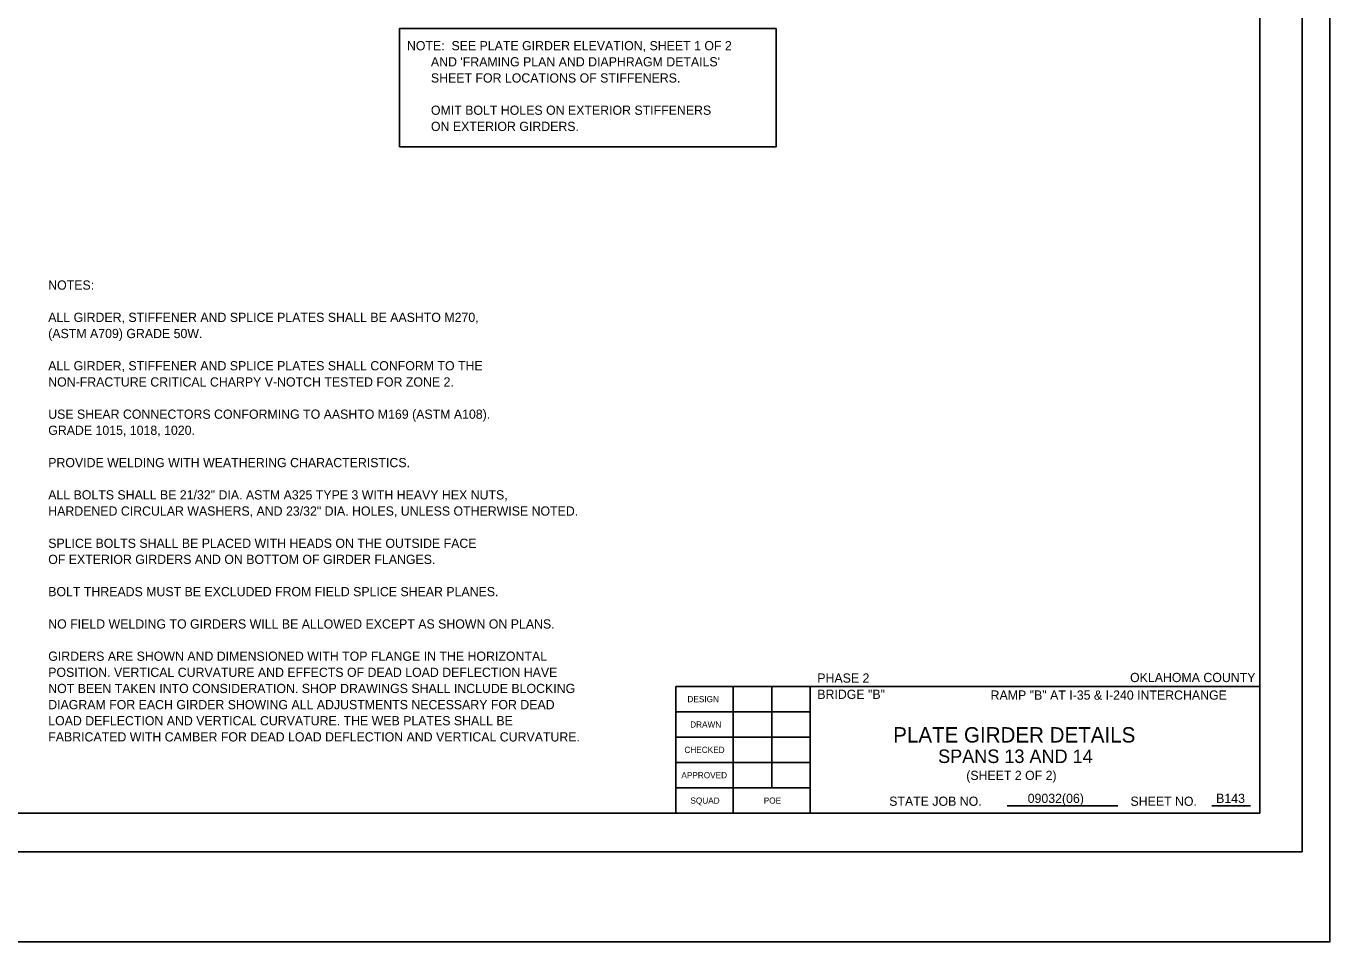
# Model space of a CAD drawing. Extents: x 4944 to 17449, y 3824 to 49087.
# Drawn here: x 14172 to 15801, y 38918 to 40062 of the extents above; entities that cross this region are included whole.
import ezdxf

# ---------------------------------------------------------------- set-up
doc = ezdxf.new("R2010")
doc.units = 0
for name, color, linetype in [('37_S_TXT', 7, 'Continuous'), ('3A', 7, 'Continuous'), ('BEAM', 7, 'Continuous'), ('DIM', 7, 'Continuous'), ('ID', 7, 'Continuous'), ('Level 14', 7, 'Continuous'), ('Level 17', 7, 'Continuous'), ('REVISED', 7, 'Continuous')]:
    doc.layers.add(name, color=color, linetype=linetype)

msp = doc.modelspace()

# ---------------------------------------------------------------- linework, layer by layer
at = {"layer": '37_S_TXT'}
msp.add_lwpolyline([(12345.1, 41222), (15801.2, 41222), (15801.2, 38917.9), (12345.1, 38917.9)], close=True, dxfattribs=at)
at = {"layer": '3A'}
msp.add_lwpolyline([(14638.8, 39911.5), (15109.3, 39911.5), (15109.3, 40059.1), (14638.8, 40059.1)], close=True, dxfattribs=at)
at = {"layer": 'DIM'}
msp.add_lwpolyline([(12502.3, 41142.8), (15766.4, 41142.8), (15766.4, 39030.7), (12502.3, 39030.7)], close=True, dxfattribs=at)
at = {"layer": 'Level 14'}
for p, q in [((14984, 39237.1), (15713.6, 39237.2)), ((14984, 39078.7), (14984, 39237.1)), ((15151.9, 39078.7), (15151.9, 39237.2)), ((15151.9, 39078.7), (15151.9, 39237.2))]:
    msp.add_line(p, q, dxfattribs=at)
msp.add_lwpolyline([(15713.6, 39078.7), (12689.5, 39078.7), (12689.5, 41094.8), (15713.6, 41094.8)], close=True, dxfattribs=at)
at = {"layer": 'Level 17'}
for p, q in [((15055.9, 39078.7), (15055.9, 39237.2)), ((15103.9, 39110.4), (15103.9, 39237.2)), ((15397.8, 39088), (15536.1, 39088)), ((15397.8, 39088), (15536.1, 39088)), ((15653.6, 39088), (15701.8, 39088)), ((15653.6, 39088), (15701.8, 39088))]:
    msp.add_line(p, q, dxfattribs=at)
for points in [[(15151.9, 39205.5), (14984, 39205.5)], [(15151.9, 39173.8), (14984, 39173.8)], [(15151.9, 39142.1), (14984, 39142.1)], [(15151.9, 39110.4), (14984, 39110.4)]]:
    msp.add_lwpolyline(points, dxfattribs=at)

# ---------------------------------------------------------------- texts
at = {"layer": '3A'}
for s, height, p in [('NOTE:  SEE PLATE GIRDER ELEVATION, SHEET 1 OF 2 ', 11.52, (14648.2, 40032)), ("       AND 'FRAMING PLAN AND DIAPHRAGM DETAILS' ", 11.52, (14648.2, 40011.9)), ('       SHEET FOR LOCATIONS OF STIFFENERS. ', 11.52, (14648.2, 39991.7)), ('       OMIT BOLT HOLES ON EXTERIOR STIFFENERS ', 11.52, (14648.2, 39951.4)), ('       ON EXTERIOR GIRDERS.', 11.52, (14648.2, 39931.2)), ('NOTES:', 11.52, (14200.1, 39732.9)), ('ALL GIRDER, STIFFENER AND SPLICE PLATES SHALL BE AASHTO M270,', 11.52, (14200.1, 39692.6)), ('(ASTM A709) GRADE 50W.', 11.52, (14200.1, 39672.4)), ('ALL GIRDER, STIFFENER AND SPLICE PLATES SHALL CONFORM TO THE', 11.52, (14200.1, 39632.1)), ('NON-FRACTURE CRITICAL CHARPY V-NOTCH TESTED FOR ZONE 2.', 11.52, (14200.1, 39611.9)), ('USE SHEAR CONNECTORS CONFORMING TO AASHTO M169 (ASTM A108).', 11.52, (14200.1, 39571.6)), ('GRADE 1015, 1018, 1020.', 11.52, (14200.1, 39551.5)), ('PROVIDE WELDING WITH WEATHERING CHARACTERISTICS.  ', 11.52, (14200.1, 39511.1)), ('ALL BOLTS SHALL BE 21/32" DIA. ASTM A325 TYPE 3 WITH HEAVY HEX NUTS, ', 11.52, (14200.1, 39470.8)), ('HARDENED CIRCULAR WASHERS, AND 23/32" DIA. HOLES, UNLESS OTHERWISE NOTED.  ', 11.52, (14200.1, 39450.6)), ('SPLICE BOLTS SHALL BE PLACED WITH HEADS ON THE OUTSIDE FACE', 11.52, (14200.1, 39410.3)), ('OF EXTERIOR GIRDERS AND ON BOTTOM OF GIRDER FLANGES.  ', 11.52, (14200.1, 39390.2)), ('BOLT THREADS MUST BE EXCLUDED FROM FIELD SPLICE SHEAR PLANES.', 11.52, (14200.1, 39349.9)), ('NO FIELD WELDING TO GIRDERS WILL BE ALLOWED EXCEPT AS SHOWN ON PLANS.', 11.52, (14200.1, 39309.5)), ('GIRDERS ARE SHOWN AND DIMENSIONED WITH TOP FLANGE IN THE HORIZONTAL', 11.52, (14200.1, 39269.2)), ('POSITION. VERTICAL CURVATURE AND EFFECTS OF DEAD LOAD DEFLECTION HAVE ', 11.52, (14200.1, 39249.1)), ('PHASE 2', 11.52, (15160.8, 39241.9)), ('OKLAHOMA COUNTY', 11.52, (15551.5, 39242.6)), ('NOT BEEN TAKEN INTO CONSIDERATION. SHOP DRAWINGS SHALL INCLUDE BLOCKING ', 11.52, (14200.1, 39228.9)), ('DIAGRAM FOR EACH GIRDER SHOWING ALL ADJUSTMENTS NECESSARY FOR DEAD ', 11.52, (14200.1, 39208.7)), ('BRIDGE "B"', 11.52, (15160.8, 39221.6)), ('RAMP "B" AT I-35 & I-240 INTERCHANGE', 11.52, (15377.3, 39220.6)), ('LOAD DEFLECTION AND VERTICAL CURVATURE. THE WEB PLATES SHALL BE ', 11.52, (14200.1, 39188.6)), ('FABRICATED WITH CAMBER FOR DEAD LOAD DEFLECTION AND VERTICAL CURVATURE.', 11.52, (14200.1, 39168.4)), ('(SHEET 2 OF 2)', 11.5, (15346.9, 39120.3)), ('09032(06)', 11.52, (15423.6, 39091.6)), ('B143', 11.52, (15659, 39091.6))]:
    msp.add_text(s, height=height, dxfattribs=at).set_placement(p)
at = {"layer": 'BEAM'}
msp.add_text('PLATE GIRDER DETAILS', height=19.2, dxfattribs=at).set_placement((15255.6, 39167.1))
at = {"layer": 'ID'}
msp.add_text('SPANS 13 AND 14', height=16.875, dxfattribs=at).set_placement((15311.7, 39141.5))
at = {"layer": 'REVISED'}
for s, height, p in [('DESIGN', 7.68, (14998.6, 39217.5)), ('DRAWN', 7.68, (15002, 39185.8)), ('CHECKED', 7.68, (14994.8, 39154.1)), ('APPROVED', 7.68, (14991, 39122.4)), ('SQUAD', 7.68, (15002.3, 39090.7)), ('POE', 7.68, (15093.9, 39090.7)), ('STATE JOB NO.', 11.52, (15250.6, 39088)), ('STATE JOB NO.', 11.52, (15250.6, 39088)), ('SHEET NO. ', 11.52, (15552, 39088)), ('SHEET NO. ', 11.52, (15552, 39088))]:
    msp.add_text(s, height=height, dxfattribs=at).set_placement(p)

doc.saveas('drawing.dxf')
